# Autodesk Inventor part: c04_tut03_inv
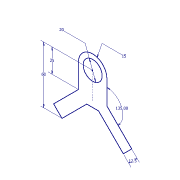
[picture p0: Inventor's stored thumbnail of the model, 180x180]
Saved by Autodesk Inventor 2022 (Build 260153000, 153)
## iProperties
Created: 2017-04
Part Number: c04_tut03_inv
Material: Generic
Document SubType Name: Modeling
Designer: CADCIM 00
Density: 1 g/cm^3
Appearance: Default
Author: CADCIM 00
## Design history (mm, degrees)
sketch "Sketch1"
  geometry: L1 (-6.25, -33.928)-(6.25, -33.928); L2 (6.25, -33.928)-(32.322, -60); L3 (32.322, -60)-(41.161, -51.161); L4 (41.161, -51.161)-(15, -25); L5 (15, -25)-(15, 0); L6 (-15, 0)-(-15, -25); L7 (-15, -25)-(-41.161, -51.161); L8 (-41.161, -51.161)-(-32.322, -60); L9 (-32.322, -60)-(-6.25, -33.928); L10 (0, 0)-(0, -28.219); C1 r 10 at (0, 0); A1 r 15 centre (0, 0) between (15, 0) and (-15, 0); 1 further point
  constraints: 20 end point, 5 perpendicular, 2 centre point, 2 coincident, 2 point on circle, 2 symmetric about line, 2 tangent, 1 concentric, 1 equal length, 1 horizontal, 1 parallel, 1 point on line, 1 vertical, 2 other
  dimensions: "d0" = 15 radius of A1; "d1" = 135 deg angle of L7 L6; "d2" = 12.5 distance of L7.end L8.end; "d3" = 60 vertical distance of L2.end L10.start; "d4" = 25 vertical distance of L10.start L4.end; "d5" = 20 diameter of C1
